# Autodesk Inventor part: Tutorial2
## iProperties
Shininess: 77.0
Length Units: 11269
Angle Units: 11279
Time Units: 11290
Mass Units: 11283
Length Display Precision: 3
Angle Display Precision: 2
Created: 2001-12
Part Number: Tutorial2
Document SubType Name: Modeling
Designer: Renu Muthoo
Density: 0.0
Volumn: 0.0
Area: 0.0
PropertySet Name: Model Information
Control State: 0
Master: False
Checked Out: False
Author: Renu Muthoo
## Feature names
1. Extrusion1
2. Extrusion2
3. Extrusion3
4. Extrusion4
5. Extrusion5
6. Mirror2
7. Hole3
